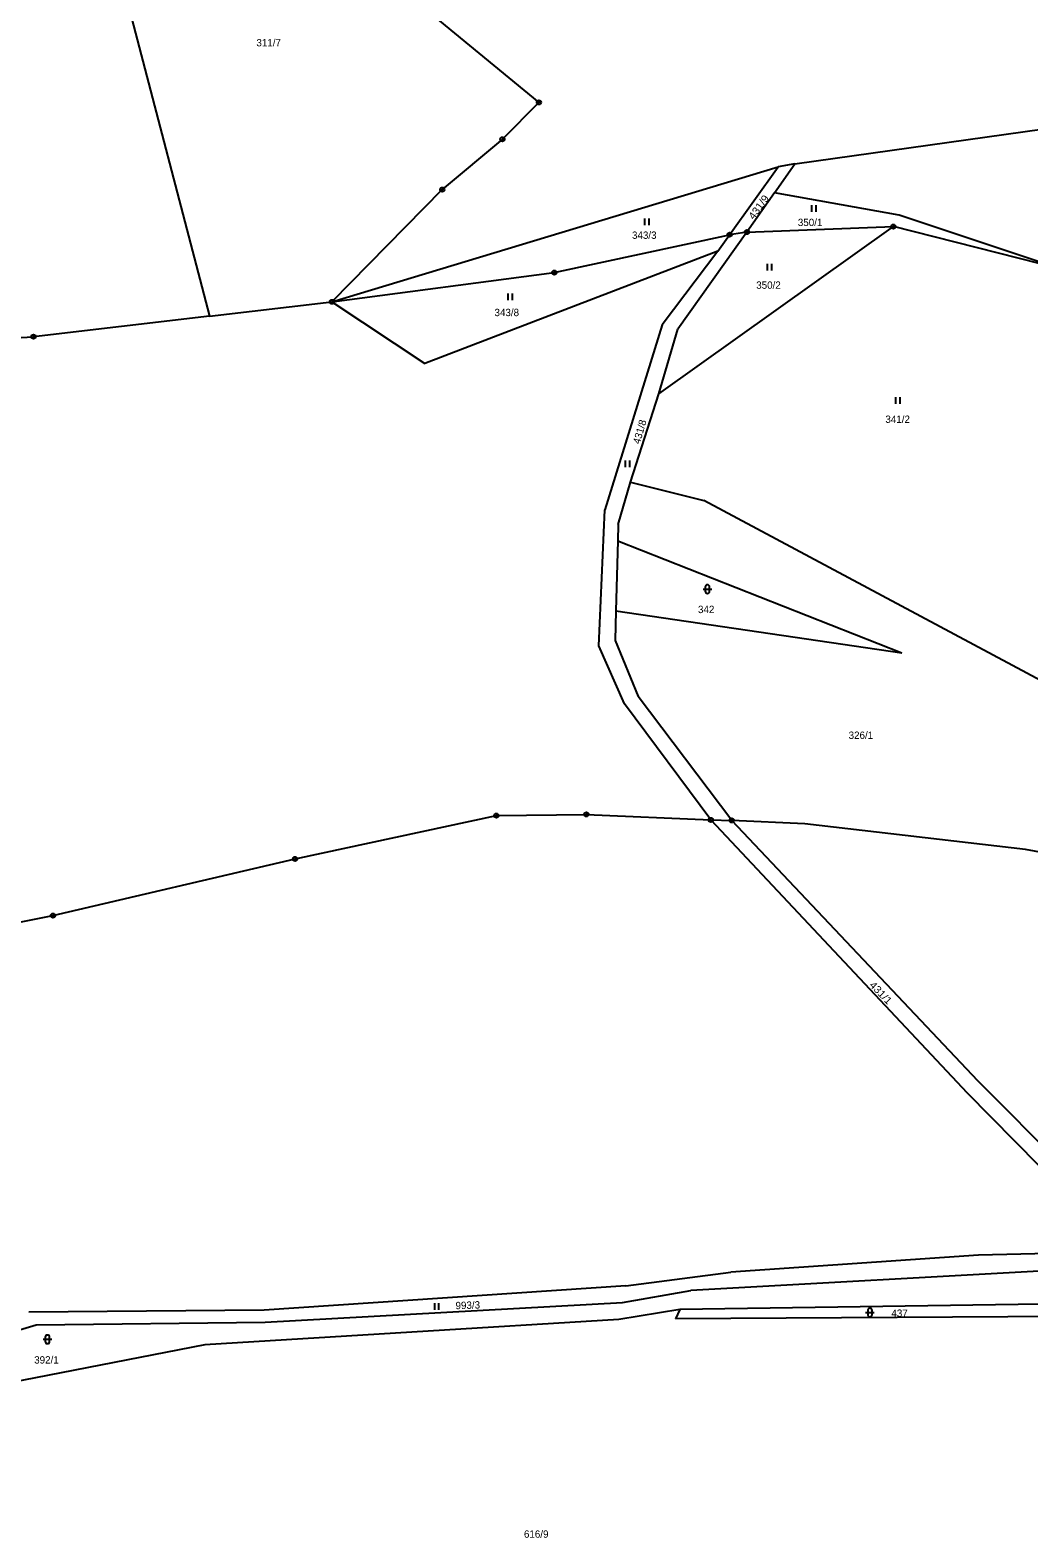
# Model space of a CAD drawing. Extents: x -754970 to -752637, y -970569 to -968179.
# Drawn here: x -754191 to -753959.6, y -968945.9 to -968596.7 of the extents above; entities that cross this region are included whole.
import ezdxf
from ezdxf.enums import TextEntityAlignment as Align

# ---------------------------------------------------------------- set-up
doc = ezdxf.new("R2010")
doc.units = 0
doc.header["$LTSCALE"] = 0.68
for name, color, linetype, lineweight in [('1', 7, 'Continuous', 25), ('3', 7, 'Continuous', 25), ('8', 7, 'Continuous', 25)]:
    doc.layers.add(name, color=color, linetype=linetype, lineweight=lineweight)
doc.layers.add('2', color=7, linetype='Continuous')

msp = doc.modelspace()

# ---------------------------------------------------------------- linework, layer by layer
at = {"layer": '1'}
for p, q in [((-754183.76, -968531.43), (-754149.44, -968662.92)), ((-754171.96, -968532.09), (-754073.1, -968613.4)), ((-754013.82, -968627.61), (-753839.61, -968603.2)), ((-754073.1, -968613.4), (-754081.56, -968621.94)), ((-754081.56, -968621.94), (-754095.49, -968633.59)), ((-754121.05, -968659.61), (-754017.72, -968628.35)), ((-754028.95, -968644.05), (-754017.72, -968628.35)), ((-754018.51, -968634.37), (-754013.82, -968627.61)), ((-754013.82, -968627.61), (-754017.72, -968628.35)), ((-754095.49, -968633.59), (-754121.05, -968659.61)), ((-754018.51, -968634.37), (-754024.92, -968643.44)), ((-753989.7, -968639.55), (-754018.51, -968634.37)), ((-754045.3, -968680.9), (-753991.01, -968642.19)), ((-754024.92, -968643.44), (-753991.01, -968642.19)), ((-753952.37, -968651.93), (-753991.01, -968642.19)), ((-753952.37, -968651.93), (-753989.7, -968639.55)), ((-754069.55, -968652.82), (-754028.95, -968644.05)), ((-754024.92, -968643.44), (-754040.97, -968665.96)), ((-754031.67, -968647.85), (-754028.95, -968644.05)), ((-754024.92, -968643.44), (-754028.95, -968644.05)), ((-754031.67, -968647.85), (-754099.51, -968673.93)), ((-754031.67, -968647.85), (-754044.59, -968664.92)), ((-754121.05, -968659.61), (-754069.55, -968652.82)), ((-754149.44, -968662.92), (-754121.05, -968659.61)), ((-754121.05, -968659.61), (-754099.51, -968673.93)), ((-754149.44, -968662.92), (-754190.19, -968667.68)), ((-754044.59, -968664.92), (-754057.81, -968707.81)), ((-754045.3, -968680.9), (-754040.97, -968665.96)), ((-754220.37, -968669.52), (-754190.19, -968667.68)), ((-754051.9, -968701.41), (-754045.3, -968680.9)), ((-754054.76, -968711.22), (-754051.9, -968701.41)), ((-754051.9, -968701.41), (-754034.95, -968705.64)), ((-753955.63, -968748.04), (-754034.95, -968705.64)), ((-754059.23, -968739.33), (-754057.81, -968707.81)), ((-754054.76, -968711.22), (-754054.83, -968715)), ((-754054.83, -968715), (-754055.27, -968731.18)), ((-754054.83, -968715), (-753989.06, -968740.9)), ((-754055.27, -968731.18), (-754055.45, -968738.03)), ((-754055.27, -968731.18), (-753989.06, -968740.9)), ((-754053.3, -968752.74), (-754059.23, -968739.33)), ((-754055.45, -968738.03), (-754050.11, -968751.04)), ((-754028.44, -968779.74), (-754050.11, -968751.04)), ((-754033.29, -968779.62), (-754053.3, -968752.74)), ((-754129.61, -968788.66), (-754082.96, -968778.61)), ((-754082.96, -968778.61), (-754062.1, -968778.35)), ((-754062.1, -968778.35), (-754033.29, -968779.62)), ((-754033.29, -968779.62), (-754028.44, -968779.74)), ((-754033.29, -968779.62), (-753973.92, -968842.88)), ((-754011.55, -968780.56), (-754028.44, -968779.74)), ((-753971.34, -968840.12), (-754028.44, -968779.74)), ((-753960.38, -968786.5), (-754011.55, -968780.56)), ((-754185.68, -968801.8), (-754129.61, -968788.66)), ((-753932.89, -968791.59), (-753960.38, -968786.5)), ((-754267.58, -968817.77), (-754185.68, -968801.8)), ((-753931.61, -968880.15), (-753971.34, -968840.12)), ((-753937.67, -968879.68), (-753973.92, -968842.88)), ((-753937.67, -968879.68), (-753971.28, -968880.45)), ((-753934.48, -968882.86), (-754037.94, -968888.61)), ((-753971.28, -968880.45), (-754028.66, -968884.41)), ((-754052.96, -968887.59), (-754028.66, -968884.41)), ((-754052.96, -968887.59), (-754136.79, -968893.18)), ((-754053.72, -968891.41), (-754037.94, -968888.61)), ((-754136.79, -968893.18), (-754191.24, -968893.69)), ((-754136.54, -968895.98), (-754053.72, -968891.41)), ((-754040.49, -968893.06), (-754054.62, -968895.34)), ((-754040.49, -968893.06), (-754041.51, -968895.23)), ((-753925.26, -968891.37), (-754040.49, -968893.06)), ((-754241.27, -968911.79), (-754189.58, -968896.62)), ((-754189.58, -968896.62), (-754136.54, -968895.98)), ((-754054.62, -968895.34), (-754150.53, -968901.2)), ((-753923.94, -968894.49), (-754041.51, -968895.23)), ((-754150.53, -968901.2), (-754199.37, -968910.74))]:
    msp.add_line(p, q, dxfattribs=at)
at = {"layer": '3'}
for p, q in [((-754009.901, -968638.75), (-754009.901, -968637.25)), ((-754008.9, -968638.75), (-754008.9, -968637.25)), ((-754048.601, -968641.84), (-754048.601, -968640.34)), ((-754047.6, -968641.84), (-754047.6, -968640.34)), ((-754020.181, -968652.32), (-754020.181, -968650.82)), ((-754019.18, -968652.32), (-754019.18, -968650.82)), ((-754080.231, -968659.2), (-754080.231, -968657.7)), ((-754079.23, -968659.2), (-754079.23, -968657.7)), ((-753990.421, -968683.23), (-753990.421, -968681.73)), ((-753989.42, -968683.23), (-753989.42, -968681.73)), ((-754053.061, -968697.88), (-754053.061, -968696.38)), ((-754052.06, -968697.88), (-754052.06, -968696.38)), ((-754035.071, -968726.151), (-754033.069, -968726.151)), ((-754034.571, -968725.651), (-754034.571, -968726.652)), ((-754033.569, -968726.652), (-754033.569, -968725.651)), ((-754097.261, -968893.08), (-754097.261, -968891.58)), ((-754096.26, -968893.08), (-754096.26, -968891.58)), ((-753997.451, -968893.761), (-753995.449, -968893.761)), ((-753996.951, -968893.261), (-753996.951, -968894.262)), ((-753995.949, -968894.262), (-753995.949, -968893.261)), ((-754187.951, -968899.951), (-754185.949, -968899.951)), ((-754187.451, -968899.451), (-754187.451, -968900.452)), ((-754186.449, -968900.452), (-754186.449, -968899.451))]:
    msp.add_line(p, q, dxfattribs=at)
for centre, start, end in [((-754034.07, -968725.6509), 0, 180), ((-754034.07, -968726.6509), 180, 359.98789), ((-753996.45, -968893.2609), 0, 180), ((-753996.45, -968894.2609), 180, 359.98789), ((-754186.95, -968899.4509), 0, 180), ((-754186.95, -968900.4509), 180, 359.98789)]:
    msp.add_arc(centre, 0.5, start, end, dxfattribs=at)
at = {"layer": '8'}
for centre, radius in [((-754073.1, -968613.3999), 0.5), ((-754073.1, -968613.3999), 0.0303), ((-754081.56, -968621.9399), 0.5), ((-754081.56, -968621.9399), 0.0303), ((-754095.49, -968633.5899), 0.5), ((-754095.49, -968633.5899), 0.0303), ((-753991.01, -968642.1899), 0.5), ((-753991.01, -968642.1899), 0.0303), ((-754028.95, -968644.0499), 0.5), ((-754028.95, -968644.0499), 0.0303), ((-754024.92, -968643.4399), 0.5), ((-754024.92, -968643.4399), 0.0303), ((-754069.55, -968652.8199), 0.5), ((-754069.55, -968652.8199), 0.0303), ((-754121.05, -968659.6099), 0.5), ((-754121.05, -968659.6099), 0.0303), ((-754190.19, -968667.6799), 0.5), ((-754190.19, -968667.6799), 0.0303), ((-754082.96, -968778.6099), 0.5), ((-754082.96, -968778.6099), 0.0303), ((-754062.1, -968778.3499), 0.5), ((-754062.1, -968778.3499), 0.0303), ((-754033.29, -968779.6199), 0.5), ((-754033.29, -968779.6199), 0.0303), ((-754028.44, -968779.7399), 0.5), ((-754028.44, -968779.7399), 0.0303), ((-754129.61, -968788.6599), 0.5), ((-754129.61, -968788.6599), 0.0303), ((-754185.68, -968801.7999), 0.5), ((-754185.68, -968801.7999), 0.0303)]:
    msp.add_circle(centre, radius, dxfattribs=at)

# ---------------------------------------------------------------- texts
at = {"layer": '2'}
for s, p in [('311/7', (-754135.71, -968600.425)), ('350/1', (-754010.29, -968642.055)), ('343/3', (-754048.71, -968645.015)), ('350/2', (-754019.93, -968656.585)), ('343/8', (-754080.56, -968662.925)), ('341/2', (-753990.01, -968687.655)), ('342', (-754034.369, -968731.715)), ('326/1', (-753998.53, -968760.855)), ('437', (-753989.569, -968894.745)), ('392/1', (-754187.19, -968905.565)), ('616/9', (-754073.74, -968945.915))]:
    msp.add_text(s, height=1.7, dxfattribs=at).set_placement(p, align=Align.CENTER)
at = {"layer": '2', "width": 1.1}
for s, rotation, p in [('431/9', 54, (-754021.5211, -968638.1751)), ('431/1', 314, (-753994.5148, -968820.2655))]:
    msp.add_text(s, height=1.7, rotation=rotation, dxfattribs=at).set_placement(p, align=Align.CENTER)
at = {"layer": '2'}
for s, rotation, p in [('431/8', 74, (-754048.9571, -968689.9378)), ('993/3', 2, (-754089.5597, -968892.8935))]:
    msp.add_text(s, height=1.7, rotation=rotation, dxfattribs=at).set_placement(p, align=Align.CENTER)

doc.saveas('drawing.dxf')
